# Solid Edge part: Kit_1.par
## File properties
Author: bmolnar
Last saved by: bmolnar
Revision: 78
Sűrűség: 0,000 kg/m^3
Pontosság: 0,990
Username: bmolnar
Dokumentum tartalom típus: 0
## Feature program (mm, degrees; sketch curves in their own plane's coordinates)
base feature "unnamed BaseFeature 1"
sketch for "unnamed Hole 1" plane through (17.575, -12.675, 4.5) normal (0, 0, -1) x-axis (0.38075, 0.924678, 0)
  hole centre (-3.8102, 0.136) bore radius 2.4585
hole "unnamed Hole 1" through
sketch for "unnamed Hole 2" plane through (17.575, -12.675, 4.5) normal (0, 0, -1) x-axis (0.38075, 0.924678, 0)
  hole centre (26.2418, -12.2384) bore radius 2.4585
hole "unnamed Hole 2" through
sketch for "unnamed Hole 3" plane through (17.575, -12.675, 4.5) normal (0, 0, -1) x-axis (0.38075, 0.924678, 0)
  hole centre (-16.1846, -29.9161) bore radius 2.4585
hole "unnamed Hole 3" through
sketch for "unnamed Hole 4" plane through (17.575, -12.675, 4.5) normal (0, 0, -1) x-axis (0.38075, 0.924678, 0)
  hole centre (13.8675, -42.2904) bore radius 2.4585
hole "unnamed Hole 4" through
pattern "unnamed Pattern 1" of "unnamed Hole 1", "unnamed Hole 2", "unnamed Hole 3", "unnamed Hole 4"
thread "unnamed Thread 1"
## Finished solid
Body 1: solid body, 293 faces, 721 edges, 450 vertices, 4 internal voids.
  Faces by surface: plane 140, cylinder 68, swept 55, torus 20, cone 9, spline 1
  Edges by curve: line 433, circle 161, spline 122, curve on surface 4, intersection 1
Bounding box of the edges (mm; curved faces can reach further): 49.000 x 49.000 x 14.100, from (-24.5, -24.5, 0) to (24.5, 24.5, 14.1).
Cylindrical faces by radius (mm): R0.2 x30, R0.335 x1, R0.5307 x1, R1.25 x1, R2.4585 x4, R2.5402 x12, R2.6 x4, R3.75 x4, R4 x4, R4.283 x1, R4.5 x5, R10.6633 x1
Conical faces (half-angle, radius in mm at the cone's reference point): 0.5 deg R8 x4, 45 deg R2.8085 x4, 45 deg R4.65 x1
Toroidal faces (ring radius, tube radius in mm): R2.9402 r0.4 x12, R3.55 r0.2 x8
Planar faces by outward normal: +x 12, +y 12, +z 1, -x 10, -y 12, -z 18, oblique 75
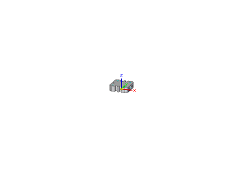
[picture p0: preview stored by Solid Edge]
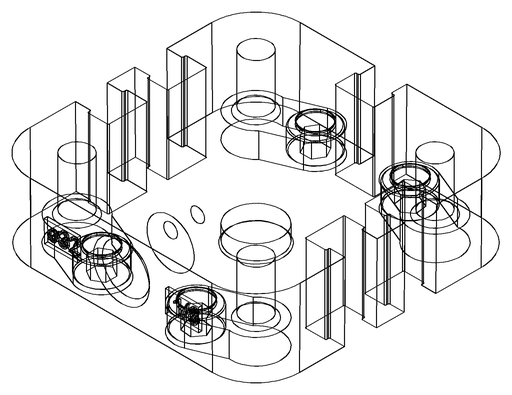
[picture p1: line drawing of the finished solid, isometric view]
